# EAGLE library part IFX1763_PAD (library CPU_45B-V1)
Infineon IFX1763 LDO with exposed pad Device: - IFX1763_PADNOP = device without solder paste on the exposed pad - IFX1763_PADWIP = device with solder paste on the exposed pad
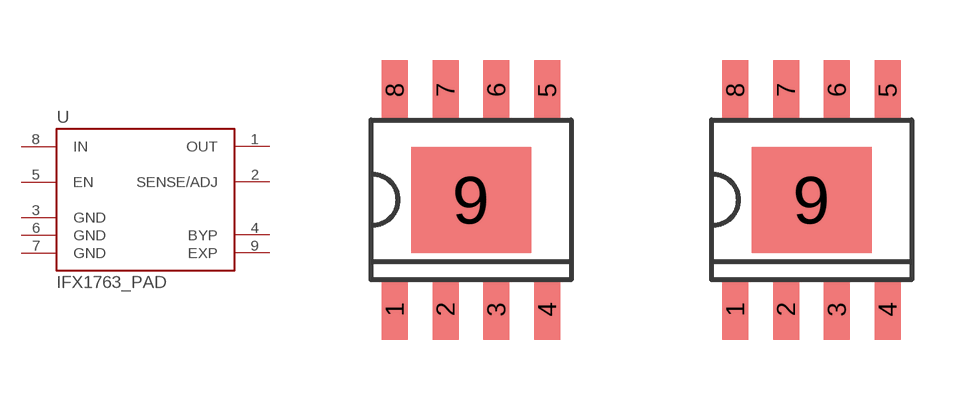
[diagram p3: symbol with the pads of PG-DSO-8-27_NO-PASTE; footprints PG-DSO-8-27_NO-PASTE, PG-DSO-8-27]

Designator prefix U

## IFX1763_PADNOP  [PG-DSO-8-27_NO-PASTE]
1  OUT  pwr
2  SENSE/ADJ  pas
3  GND  pwr
4  BYP  pas
5  EN  in
6  GND  pwr
7  GND  pwr
8  IN  pwr
9  EXP  pwr

## IFX1763_PADWIP  [PG-DSO-8-27]
Pads as for PG-DSO-8-27_NO-PASTE

## Footprint PG-DSO-8-27_NO-PASTE (pad centres in mm)
Infineon P/PG-DSO-8-27 (exposed Pad) footprint NO SOLDERPASTE ON EXPOSED PAD
smd 0.65 x 1.51: 1 -1.905,-2.745; 2 -0.635,-2.745; 3 0.635,-2.745; 4 1.905,-2.745; 5 1.905,2.745; 6 0.635,2.745; 7 -0.635,2.745; 8 -1.905,2.745
smd 3 x 2.65: 9 0,0

## Footprint PG-DSO-8-27 (pad centres in mm)
Infineon P/PG-DSO-8-27 (exposed Pad) footprint
smd 0.65 x 1.51: 1 -1.905,-2.745; 2 -0.635,-2.745; 3 0.635,-2.745; 4 1.905,-2.745; 5 1.905,2.745; 6 0.635,2.745; 7 -0.635,2.745; 8 -1.905,2.745
smd 3 x 2.65: 9 0,0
